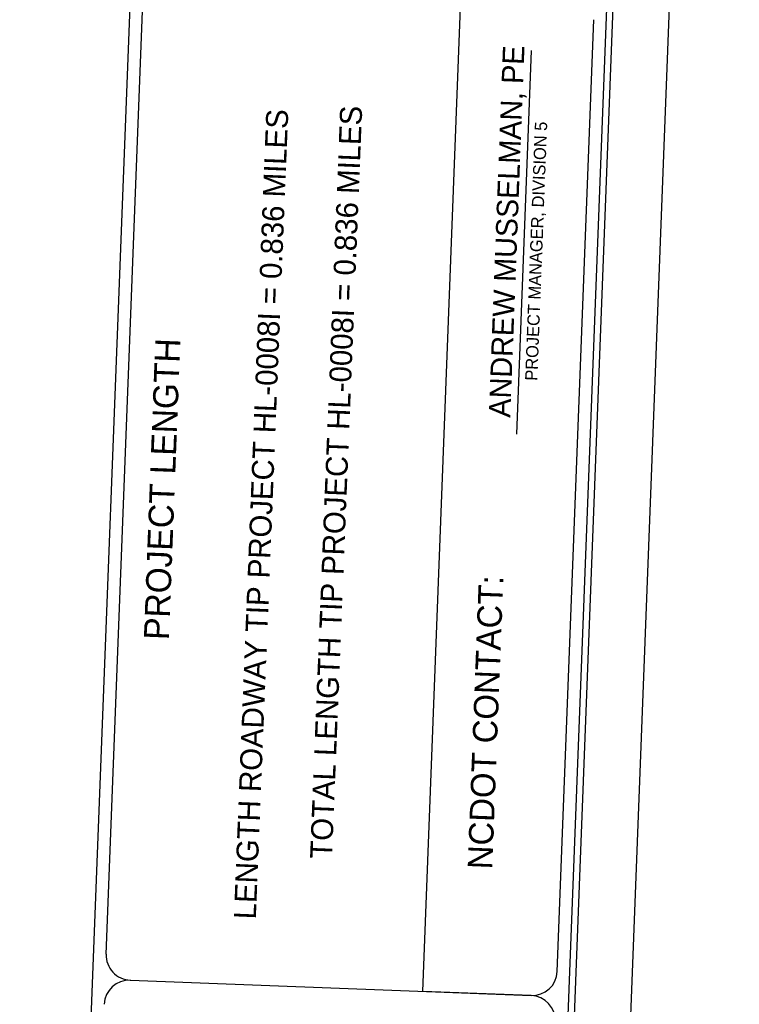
# Model space of a CAD drawing. Extents: x 2094564 to 2100382, y 679033 to 692366.
# Drawn here: x 2098948 to 2100382, y 684877 to 686841 of the extents above; entities that cross this region are included whole.
import ezdxf

# ---------------------------------------------------------------- set-up
doc = ezdxf.new("R2010")
doc.units = 0
for name, color, linetype in [('Prop EOT', 7, 'Continuous'), ('Prop Horizontal Alignment Direction Label', 7, 'Continuous'), ('Prop Horizontal Alignment Tick Label', 7, 'Continuous'), ('Prop Horizontal Alignment Tick Large', 7, 'Continuous'), ('Scratch_Level_0', 7, 'Continuous')]:
    doc.layers.add(name, color=color, linetype=linetype)

msp = doc.modelspace()

# ---------------------------------------------------------------- linework, layer by layer
at = {"layer": 'Prop EOT'}
msp.add_lwpolyline([(2099967.1, 684894.2), (2099751.5, 684902.4), (2099828.1, 686901.2), (2100041.6, 686892.9)], dxfattribs=at)
at = {"layer": 'Prop Horizontal Alignment Direction Label'}
for p, q in [((2099030, 683278.9), (2099302.1, 690373.6)), ((2099120.2, 684976.7), (2099193, 686875.3)), ((2099938.6, 686014.3), (2099967.9, 686779.6)), ((2099168.2, 684924.8), (2099967.6, 684894.1))]:
    msp.add_line(p, q, dxfattribs=at)
for points in [[(2099968.8, 682967.7), (2100252.4, 690362.2)], [(2100019.5, 684942.2), (2100092.4, 686840.8)]]:
    msp.add_lwpolyline(points, dxfattribs=at)
for centre, start, end in [((2099169.9, 684974.8), 177.8037, 267.8037), ((2099969.3, 684944.1), 267.8037, 357.8037), ((2099166, 684874.8), 87.8037, 177.8037), ((2099965.5, 684844.2), 357.8037, 87.8037)]:
    msp.add_arc(centre, 50, start, end, dxfattribs=at)
at = {"layer": 'Prop Horizontal Alignment Tick Label'}
msp.add_lwpolyline([(2099950.1, 682147.8), (2100269.5, 690474.2), (2094997.8, 690676.3), (2094678.5, 682349.9)], close=True, dxfattribs=at)
at = {"layer": 'Prop Horizontal Alignment Tick Large'}
msp.add_lwpolyline([(2094886.5, 690703.1), (2094563.9, 682289.3), (2100059.8, 682078.5), (2100382.4, 690492.3)], close=True, dxfattribs=at)

# ---------------------------------------------------------------- texts
at = {"layer": 'Prop Horizontal Alignment Direction Label'}
for s, height, p in [('PROJECT MANAGER, DIVISION 5', 24.505, (2099979.7, 686120.2)), ('PROJECT LENGTH', 49.998, (2099245, 685602.8)), ('NCDOT CONTACT:', 49.012, (2099889.7, 685145.4))]:
    msp.add_text(s, height=height, rotation=87.8037, dxfattribs=at).set_placement(p)
at = {"layer": 'Scratch_Level_0'}
for s, height, rotation, p in [('ANDREW MUSSELMAN, PE', 42.887, 87.8037, (2099925.7, 686046.5)), ('LENGTH ROADWAY TIP PROJECT HL-0008I = 0.836 MILES', 43.825, 87.6965, (2099418.3, 685045.7)), ('TOTAL LENGTH TIP PROJECT HL-0008I = 0.836 MILES', 43.825, 87.6965, (2099570.2, 685166.4))]:
    msp.add_text(s, height=height, rotation=rotation, dxfattribs=at).set_placement(p)

doc.saveas('drawing.dxf')
